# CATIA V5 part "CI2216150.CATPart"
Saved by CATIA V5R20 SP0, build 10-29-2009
Part number: CI2216150
Bounding box of the stored display mesh (mm): x -15 to 15, y -10.788 to 174, z -21.241 to 16.291
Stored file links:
  C:\Users\Raffaele\Desktop\3D X SITO CF\BOLEX\19-INCLINED ASSEMBLY REF_CI\CI2216150.CATPart
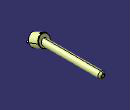
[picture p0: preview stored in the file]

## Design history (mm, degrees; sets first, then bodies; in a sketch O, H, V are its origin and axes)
Set1
  DatumSurface1 to DatumSurface16 "MANIFOLD_SOLID_BREP #385"
  DatumSurface17 to DatumSurface39 "MANIFOLD_SOLID_BREP #1143"
Body1 (main body)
